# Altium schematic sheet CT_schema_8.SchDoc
size 278 x 170 mm
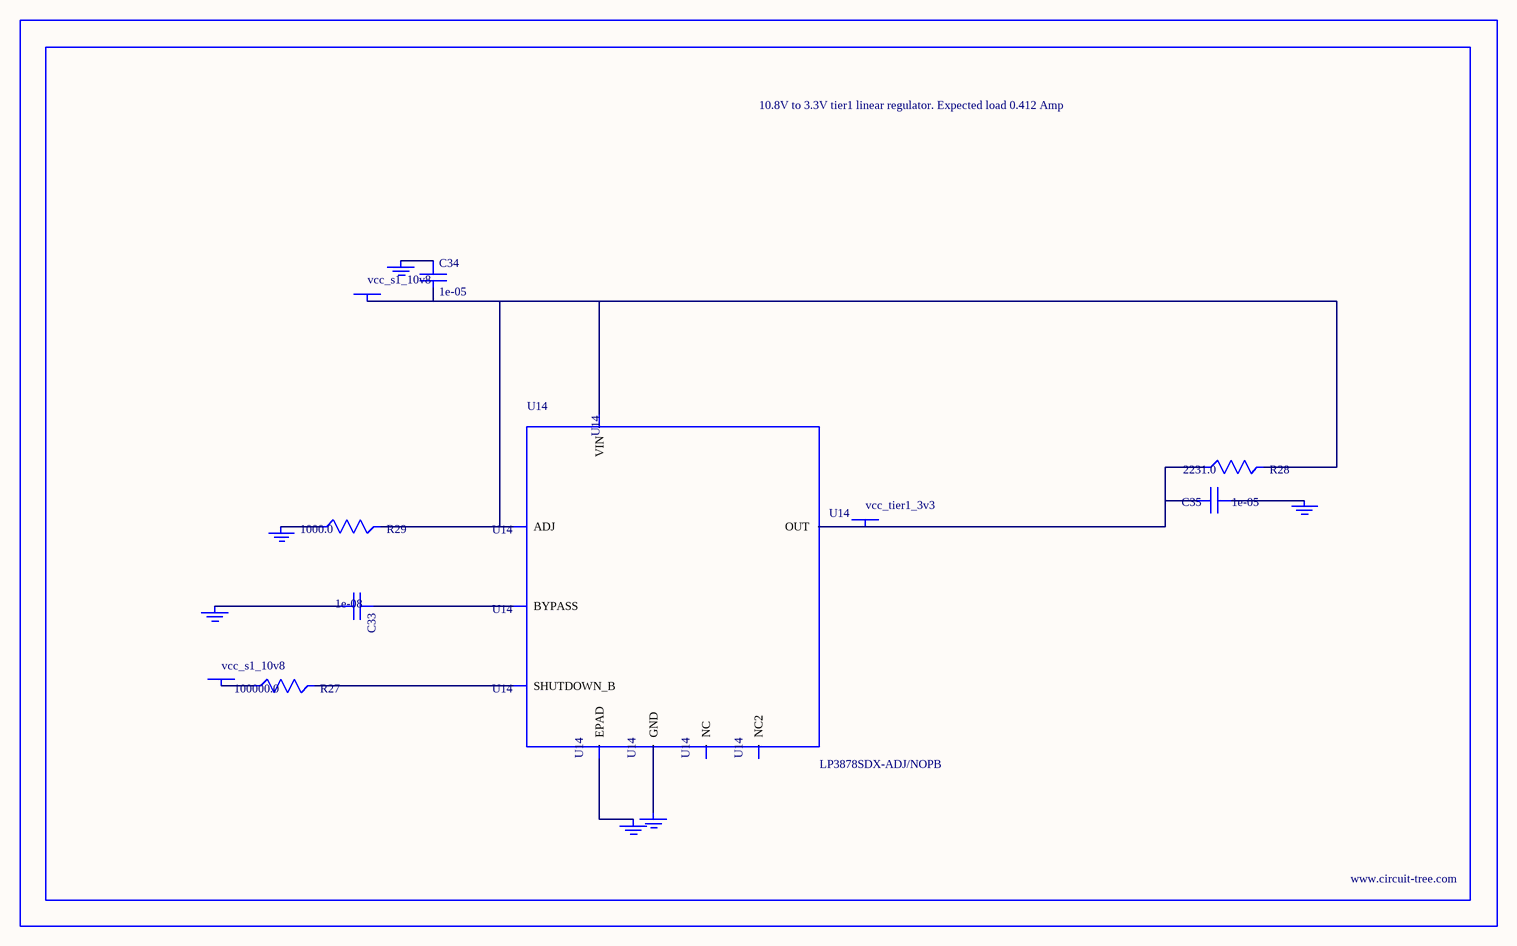
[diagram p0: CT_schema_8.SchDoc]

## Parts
BORDER7  (no value)
C33  1e-08  [C0402]
C34  1e-05  [C1206]
C35  1e-05  [C1210]
GND_INSTANCE_7_0  (no value)
GND_INSTANCE_7_1  (no value)
GND_INSTANCE_7_2  (no value)
GND_INSTANCE_7_3  (no value)
GND_INSTANCE_7_4  (no value)
GND_INSTANCE_7_5  (no value)
POWER_INSTANCE_7_0  vcc_s1_10v8
POWER_INSTANCE_7_1  vcc_s1_10v8
POWER_INSTANCE_7_2  vcc_tier1_3v3
R27  100000.0  [R0603]
R28  2231.0  [R0603]
R29  1000.0  [R0603]
U14  LP3878SDX-ADJ/NOPB  [WSON-8]

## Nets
NetC33_1: C33.1 U14.1(BYPASS)
NetC33_2: C33.2 GND_INSTANCE_7_0.0(GND)
NetC34_1: C34.1 GND_INSTANCE_7_1.0(GND)
NetC34_2: C34.2 POWER_INSTANCE_7_0.0(PWR) R28.2 R29.2 U14.4(VIN) U14.6(ADJ)
NetC35_1: C35.1 GND_INSTANCE_7_2.0(GND)
NetC35_2: C35.2 POWER_INSTANCE_7_2.0(PWR) R28.1 U14.5(OUT)
NetGND_INSTANCE_7_3_0: GND_INSTANCE_7_3.0(GND) R29.1
NetGND_INSTANCE_7_4_0: GND_INSTANCE_7_4.0(GND) U14.PAD(EPAD)
NetGND_INSTANCE_7_5_0: GND_INSTANCE_7_5.0(GND) U14.3(GND)
NetPOWER_INSTANCE_7_1_0: POWER_INSTANCE_7_1.0(PWR) R27.1
NetR27_2: R27.2 U14.8(SHUTDOWN_B)

Not connected (* = marked no-connect by the designer): U14 2(NC) 7(NC2)

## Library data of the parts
BORDER7 = BORDER_PAGE7
C33 = C0402C103K3RAC
C34 = C1206C106K3RACTU
C35 = GRM32DR61E106MA12L
GND_INSTANCE_7_0-GND_INSTANCE_7_5 = GND
POWER_INSTANCE_7_0-POWER_INSTANCE_7_2 = PWR
R27 = RC0603JR-07100KL
R28 = R28
R29 = RC0603JR-071KL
